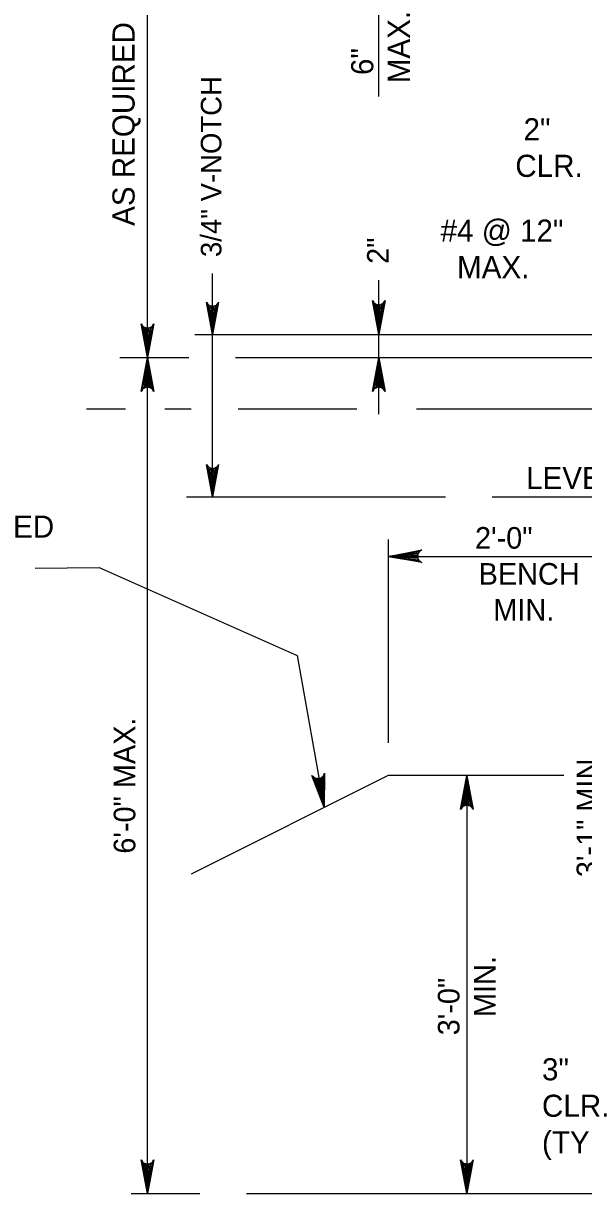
# Model space of a CAD drawing. Extents: x 638167 to 640248, y 296544 to 298920.
# Drawn here: x 639469.7 to 639551.3, y 298650.7 to 298821.3 of the extents above; entities that cross this region are included whole.
import ezdxf

# ---------------------------------------------------------------- set-up
doc = ezdxf.new("R2010")
doc.units = 0
doc.layers.add('1', color=7, linetype='Continuous')

msp = doc.modelspace()

# ---------------------------------------------------------------- linework, layer by layer
at = {"layer": '1'}
for p, q in [((639521.48, 298810.67), (639521.48, 298853.73)), ((639487.76, 298772.6), (639487.76, 298843.72)), ((639497.24, 298752.31), (639497.24, 298784.89)), ((639521.48, 298764.35), (639521.48, 298783.89)), ((639494.68, 298775.98), (639561.79, 298775.98)), ((639483.74, 298772.6), (639493.79, 298772.6)), ((639487.76, 298650.66), (639487.76, 298772.6)), ((639500.61, 298772.6), (639566.49, 298772.6)), ((639484.54, 298765.07), (639478.88, 298765.07)), ((639494.14, 298765.07), (639490.29, 298765.07)), ((639518.28, 298765.07), (639500.96, 298765.07)), ((639559.32, 298765.07), (639526.99, 298765.07)), ((639493.43, 298752.31), (639531.21, 298752.31)), ((639538.03, 298752.31), (639561.79, 298752.31)), ((639522.84, 298746.05), (639522.84, 298716.4)), ((639522.84, 298743.61), (639563.48, 298743.61)), ((639471.38, 298741.89), (639480.73, 298741.98)), ((639480.73, 298741.98), (639509.56, 298729.15)), ((639509.56, 298729.15), (639513.51, 298706.96)), ((639522.84, 298711.62), (639494.14, 298697.27)), ((639548.47, 298711.62), (639522.84, 298711.62)), ((639534.34, 298711.62), (639534.34, 298650.66)), ((639485.37, 298650.66), (639495.38, 298650.66)), ((639502.18, 298650.66), (639560.34, 298650.66))]:
    msp.add_line(p, q, dxfattribs=at)
for points in [[(639497.24, 298775.98), (639496.36, 298780.68), (639496.49, 298780.5), (639496.61, 298780.32), (639496.77, 298780.22), (639496.93, 298780.13), (639497.08, 298780.1), (639497.24, 298780.08), (639497.4, 298780.1), (639497.56, 298780.13), (639497.71, 298780.22), (639497.87, 298780.32), (639498, 298780.5), (639498.12, 298780.68), (639497.24, 298775.98), (639498, 298780.5), (639497.87, 298780.32), (639497.24, 298775.98), (639497.71, 298780.22), (639497.56, 298780.13), (639497.24, 298775.98), (639497.4, 298780.1), (639497.24, 298780.08), (639497.24, 298775.98), (639497.08, 298780.1), (639496.93, 298780.13), (639497.24, 298775.98), (639496.77, 298780.22), (639496.61, 298780.32), (639497.24, 298775.98), (639496.49, 298780.5)], [(639521.48, 298775.98), (639520.56, 298780.91), (639520.69, 298780.72), (639520.82, 298780.53), (639520.99, 298780.44), (639521.15, 298780.34), (639521.32, 298780.31), (639521.48, 298780.28), (639521.65, 298780.31), (639521.81, 298780.34), (639521.98, 298780.44), (639522.14, 298780.53), (639522.28, 298780.72), (639522.41, 298780.91), (639521.48, 298775.98), (639522.28, 298780.72), (639522.14, 298780.53), (639521.48, 298775.98), (639521.98, 298780.44), (639521.81, 298780.34), (639521.48, 298775.98), (639521.65, 298780.31), (639521.48, 298780.28), (639521.48, 298775.98), (639521.32, 298780.31), (639521.15, 298780.34), (639521.48, 298775.98), (639520.99, 298780.44), (639520.82, 298780.53), (639521.48, 298775.98), (639520.69, 298780.72)], [(639487.76, 298772.6), (639486.83, 298777.53), (639486.97, 298777.34), (639487.1, 298777.15), (639487.26, 298777.05), (639487.43, 298776.95), (639487.59, 298776.92), (639487.76, 298776.9), (639487.92, 298776.92), (639488.09, 298776.95), (639488.25, 298777.05), (639488.42, 298777.15), (639488.55, 298777.34), (639488.68, 298777.53), (639487.76, 298772.6), (639488.55, 298777.34), (639488.42, 298777.15), (639487.76, 298772.6), (639488.25, 298777.05), (639488.09, 298776.95), (639487.76, 298772.6), (639487.92, 298776.92), (639487.76, 298776.9), (639487.76, 298772.6), (639487.59, 298776.92), (639487.43, 298776.95), (639487.76, 298772.6), (639487.26, 298777.05), (639487.1, 298777.15), (639487.76, 298772.6), (639486.97, 298777.34)], [(639487.76, 298772.6), (639488.68, 298767.66), (639488.55, 298767.85), (639488.42, 298768.04), (639488.25, 298768.14), (639488.09, 298768.24), (639487.92, 298768.27), (639487.76, 298768.3), (639487.59, 298768.27), (639487.43, 298768.24), (639487.26, 298768.14), (639487.1, 298768.04), (639486.97, 298767.85), (639486.83, 298767.66), (639487.76, 298772.6), (639486.97, 298767.85), (639487.1, 298768.04), (639487.76, 298772.6), (639487.26, 298768.14), (639487.43, 298768.24), (639487.76, 298772.6), (639487.59, 298768.27), (639487.76, 298768.3), (639487.76, 298772.6), (639487.92, 298768.27), (639488.09, 298768.24), (639487.76, 298772.6), (639488.25, 298768.14), (639488.42, 298768.04), (639487.76, 298772.6), (639488.55, 298767.85)], [(639521.48, 298772.6), (639522.41, 298767.66), (639522.28, 298767.85), (639522.14, 298768.04), (639521.98, 298768.14), (639521.81, 298768.24), (639521.65, 298768.27), (639521.48, 298768.3), (639521.32, 298768.27), (639521.15, 298768.24), (639520.99, 298768.14), (639520.82, 298768.04), (639520.69, 298767.85), (639520.56, 298767.66), (639521.48, 298772.6), (639520.69, 298767.85), (639520.82, 298768.04), (639521.48, 298772.6), (639520.99, 298768.14), (639521.15, 298768.24), (639521.48, 298772.6), (639521.32, 298768.27), (639521.48, 298768.3), (639521.48, 298772.6), (639521.65, 298768.27), (639521.81, 298768.24), (639521.48, 298772.6), (639521.98, 298768.14), (639522.14, 298768.04), (639521.48, 298772.6), (639522.28, 298767.85)], [(639497.24, 298752.31), (639496.36, 298757.01), (639496.49, 298756.83), (639496.61, 298756.65), (639496.77, 298756.55), (639496.93, 298756.46), (639497.08, 298756.43), (639497.24, 298756.4), (639497.4, 298756.43), (639497.56, 298756.46), (639497.71, 298756.55), (639497.87, 298756.65), (639498, 298756.83), (639498.12, 298757.01), (639497.24, 298752.31), (639498, 298756.83), (639497.87, 298756.65), (639497.24, 298752.31), (639497.71, 298756.55), (639497.56, 298756.46), (639497.24, 298752.31), (639497.4, 298756.43), (639497.24, 298756.4), (639497.24, 298752.31), (639497.08, 298756.43), (639496.93, 298756.46), (639497.24, 298752.31), (639496.77, 298756.55), (639496.61, 298756.65), (639497.24, 298752.31), (639496.49, 298756.83)], [(639522.84, 298743.61), (639527.77, 298744.54), (639527.58, 298744.41), (639527.39, 298744.27), (639527.29, 298744.11), (639527.19, 298743.94), (639527.16, 298743.78), (639527.14, 298743.61), (639527.16, 298743.45), (639527.19, 298743.28), (639527.29, 298743.12), (639527.39, 298742.95), (639527.58, 298742.82), (639527.77, 298742.69), (639522.84, 298743.61), (639527.58, 298742.82), (639527.39, 298742.95), (639522.84, 298743.61), (639527.29, 298743.12), (639527.19, 298743.28), (639522.84, 298743.61), (639527.16, 298743.45), (639527.14, 298743.61), (639522.84, 298743.61), (639527.16, 298743.78), (639527.19, 298743.94), (639522.84, 298743.61), (639527.29, 298744.11), (639527.39, 298744.27), (639522.84, 298743.61), (639527.58, 298744.41)], [(639513.51, 298706.96), (639511.74, 298711.65), (639511.9, 298711.49), (639512.06, 298711.32), (639512.24, 298711.25), (639512.42, 298711.19), (639512.59, 298711.19), (639512.76, 298711.19), (639512.92, 298711.25), (639513.07, 298711.3), (639513.22, 298711.43), (639513.36, 298711.55), (639513.46, 298711.76), (639513.56, 298711.97), (639513.51, 298706.96), (639513.46, 298711.76), (639513.36, 298711.55), (639513.51, 298706.96), (639513.22, 298711.43), (639513.07, 298711.3), (639513.51, 298706.96), (639512.92, 298711.25), (639512.76, 298711.19), (639513.51, 298706.96), (639512.59, 298711.19), (639512.42, 298711.19), (639513.51, 298706.96), (639512.24, 298711.25), (639512.06, 298711.32), (639513.51, 298706.96), (639511.9, 298711.49)], [(639534.34, 298711.62), (639535.26, 298706.69), (639535.13, 298706.88), (639535, 298707.07), (639534.84, 298707.16), (639534.67, 298707.26), (639534.5, 298707.29), (639534.34, 298707.32), (639534.17, 298707.29), (639534.01, 298707.26), (639533.84, 298707.16), (639533.68, 298707.07), (639533.55, 298706.88), (639533.41, 298706.69), (639534.34, 298711.62), (639533.55, 298706.88), (639533.68, 298707.07), (639534.34, 298711.62), (639533.84, 298707.16), (639534.01, 298707.26), (639534.34, 298711.62), (639534.17, 298707.29), (639534.34, 298707.32), (639534.34, 298711.62), (639534.5, 298707.29), (639534.67, 298707.26), (639534.34, 298711.62), (639534.84, 298707.16), (639535, 298707.07), (639534.34, 298711.62), (639535.13, 298706.88)], [(639487.76, 298650.66), (639486.83, 298655.59), (639486.97, 298655.4), (639487.1, 298655.21), (639487.26, 298655.11), (639487.43, 298655.02), (639487.59, 298654.99), (639487.76, 298654.96), (639487.92, 298654.99), (639488.09, 298655.02), (639488.25, 298655.11), (639488.42, 298655.21), (639488.55, 298655.4), (639488.68, 298655.59), (639487.76, 298650.66), (639488.55, 298655.4), (639488.42, 298655.21), (639487.76, 298650.66), (639488.25, 298655.11), (639488.09, 298655.02), (639487.76, 298650.66), (639487.92, 298654.99), (639487.76, 298654.96), (639487.76, 298650.66), (639487.59, 298654.99), (639487.43, 298655.02), (639487.76, 298650.66), (639487.26, 298655.11), (639487.1, 298655.21), (639487.76, 298650.66), (639486.97, 298655.4)], [(639534.34, 298650.66), (639533.41, 298655.59), (639533.55, 298655.4), (639533.68, 298655.21), (639533.84, 298655.11), (639534.01, 298655.02), (639534.17, 298654.99), (639534.34, 298654.96), (639534.5, 298654.99), (639534.67, 298655.02), (639534.84, 298655.11), (639535, 298655.21), (639535.13, 298655.4), (639535.26, 298655.59), (639534.34, 298650.66), (639535.13, 298655.4), (639535, 298655.21), (639534.34, 298650.66), (639534.84, 298655.11), (639534.67, 298655.02), (639534.34, 298650.66), (639534.5, 298654.99), (639534.34, 298654.96), (639534.34, 298650.66), (639534.17, 298654.99), (639534.01, 298655.02), (639534.34, 298650.66), (639533.84, 298655.11), (639533.68, 298655.21), (639534.34, 298650.66), (639533.55, 298655.4)]]:
    msp.add_lwpolyline(points, dxfattribs=at)

# ---------------------------------------------------------------- texts
for s, height, p in [('MAX.', 3.226, (639526.01, 298812.62)), ('AS REQUIRED', 3.2256, (639485.88, 298791.81)), (' 6"', 3.226, (639520.68, 298812.62)), ('3/4" V-NOTCH', 3, (639498.54, 298787.27)), ('2"', 3.15, (639522.93, 298786.27)), ('6\'-0" MAX.', 3.15, (639485.99, 298700.24)), ('3\'-1" MIN.', 3.15, (639553.47, 298696.82)), ('MIN.', 3.15, (639538.5, 298676.41)), ('3\'-0"', 3.15, (639533.25, 298673.75))]:
    msp.add_text(s, height=height, rotation=90, dxfattribs=at).set_placement(p)
for s, height, p in [(' 2"', 3.226, (639541.39, 298804.29)), ('CLR.', 3.226, (639541.39, 298798.96)), ('#4 @ 12"', 3.226, (639530.5, 298789.51)), ('  MAX.', 3.226, (639530.5, 298784.18)), ('LEVEL', 3.226, (639542.96, 298753.43)), ('APPROX. FINISHED', 3.2256, (639433.65, 298746.34)), ('2\'-0"', 3.15, (639535.51, 298744.73)), ('BENCH', 3.15, (639536.03, 298739.48)), ('MIN.', 3.15, (639538.18, 298734.23)), ('3"', 3.226, (639545.28, 298667.18)), ('CLR.', 3.226, (639545.28, 298661.86)), ('(TYP.)', 3.226, (639545.28, 298656.53))]:
    msp.add_text(s, height=height, dxfattribs=at).set_placement(p)

doc.saveas('drawing.dxf')
